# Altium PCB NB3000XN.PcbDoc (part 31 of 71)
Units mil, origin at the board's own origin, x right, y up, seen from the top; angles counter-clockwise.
Board outline 9527.56 x 6929.77 mil, 6 copper layers (Top Layer, GND+SHIELD, MidLayer1, MidLayer2, P2 - 3V3+5V0, Bottom Layer), stack 62.375 mil thick; 832 components, 1027 nets, 4655 pads, 4981 vias.
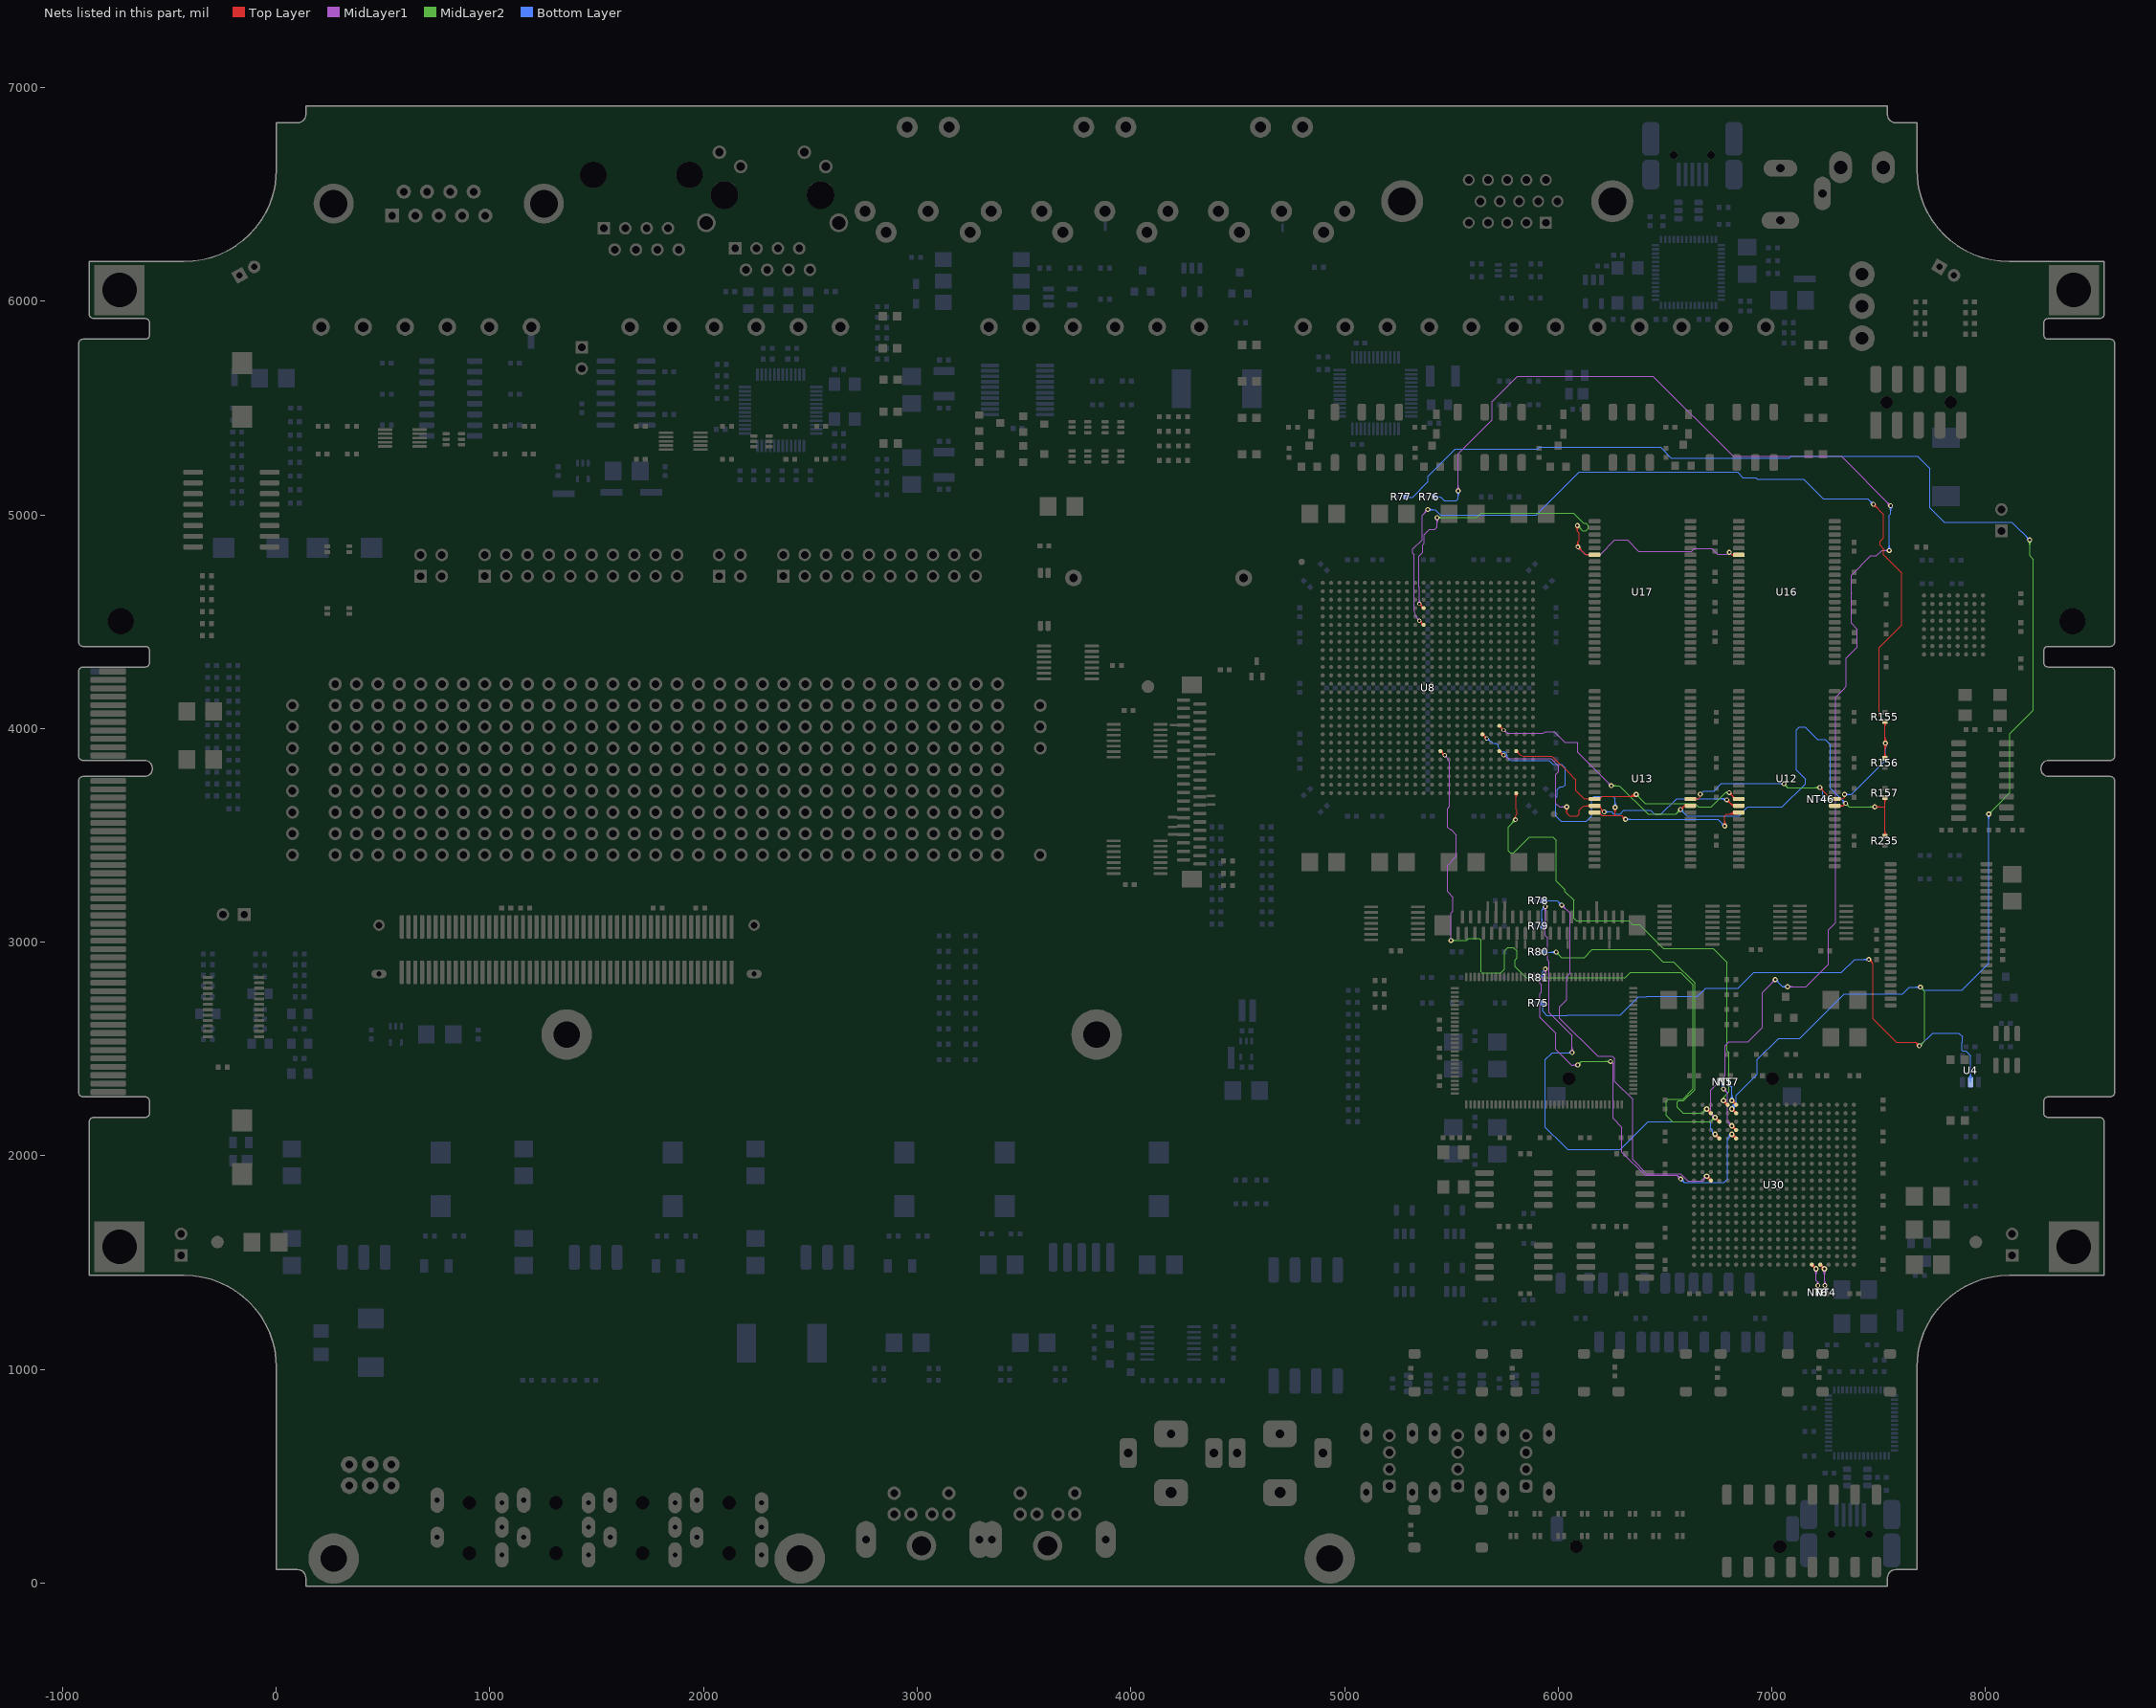
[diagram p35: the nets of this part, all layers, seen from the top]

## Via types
v1: diameter 23, hole 11.81, Top Layer to Bottom Layer, 3672 vias
v2: diameter 26, hole 11.81, Top Layer to Bottom Layer, 461 vias
v3: diameter 19, hole 11.81, Top Layer to Bottom Layer, tented both sides, 396 vias
v4: diameter 23.62, hole 11.81, Top Layer to Bottom Layer, 288 vias
v5: diameter 20, hole 11.81, Top Layer to Bottom Layer, 91 vias
v6: diameter 23, hole 11.81, Top Layer to Bottom Layer, tented both sides, 50 vias
v7: diameter 31, hole 11.81, Top Layer to Bottom Layer, 15 vias
v8: diameter 27.56, hole 11.81, Top Layer to Bottom Layer, tented both sides, 4 vias
v9: diameter 29, hole 11.81, Top Layer to Bottom Layer, 3 vias
v10: diameter 21, hole 11.81, Top Layer to Bottom Layer, 1 vias

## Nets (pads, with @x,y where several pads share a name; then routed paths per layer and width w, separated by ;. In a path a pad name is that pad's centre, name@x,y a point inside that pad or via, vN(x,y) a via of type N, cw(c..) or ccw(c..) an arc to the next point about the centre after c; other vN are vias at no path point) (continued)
DB_MEM.BUS_SDRAM_CKE: R157.2 R235.1 U8.V22 U12.37 U13.37 | length 3869.1
  Top Layer w4: U8.V22@5724.65,4005.33 cw(c5724.65,3987.23) 5737.45,4000.03 cw(c5750.25,4012.83) U8.V22@5732.15,4012.83 ; U8.V22@5724.65,4005.49 cw(c5724.65,3987.77) 5737.18,4000.3 cw(c5749.71,4012.83) U8.V22@5731.99,4012.83 ; U8.V22@5724.65,4012.83 v3(5744.33,3993.15) ; v1(6572.86,3621.04) 6590.83,3639.02 ; v1@6572.86,3626.54 ccw(c6572.86,3639.82) 6582.25,3630.43 ccw(c6591.64,3621.04) v1@6578.36,3621.04 ; v1@6572.86,3630.54 ccw(c6572.86,3653.48) 6589.07,3637.26 ccw(c6605.29,3621.04) v1@6582.36,3621.04 ; v1@6576.21,3624.4 cw(c6601.85,3598.76) U13.37@6601.85,3635.02 ; 6583.04,3631.22 cw(c6601.85,3612.41) U13.37@6601.85,3639.02 ; 6589.87,3638.05 cw(c6601.85,3626.07) U13.37@6601.85,3643.02 ; U13.37@6594.24,3636.54 ccw(c6590.83,3635.43) 6590.83,3639.02 ; U13.37@6594.24,3641.49 cw(c6590.83,3642.6) 6590.83,3639.02 ; U13.37@6619.41,3639.02 6590.83,3639.02 ; U12.37@7294.41,3639.02 7334.17,3639.02 v1(7345.19,3650.04) ; U12.37@7317.63,3633.36 cw(c7331.28,3619.7) 7331.28,3639.02 cw(c7331.28,3658.33) U12.37@7317.63,3644.67 ; v1(7481.86,3633.37) 7528.37,3633.37 7530,3635 ; v1@7485.75,3629.49 cw(c7495.14,3620.1) 7495.14,3633.37 cw(c7495.14,3646.65) v1@7485.75,3637.26 ; v1@7488.57,3626.66 cw(c7504.79,3610.44) 7504.79,3633.37 cw(c7504.79,3656.31) v1@7488.57,3640.09 ; R235.1@7523.41,3502.62 ccw(c7507.5,3518.52) 7530,3518.52 ccw(c7552.5,3518.52) R235.1@7536.59,3502.62 ; R157.2@7523.41,3671.01 cw(c7507.5,3655.1) 7530,3655.1 cw(c7552.5,3655.1) R157.2@7536.59,3671.01 ; R157.2@7524.23,3670.28 cw(c7514.83,3658.38) 7530,3658.38 ; R235.1@7526.24,3499.79 ccw(c7517.16,3508.87) 7530,3508.87 ccw(c7542.84,3508.87) R235.1@7533.76,3499.79 ; R157.2@7526.24,3673.84 cw(c7517.16,3664.76) 7530,3664.76 cw(c7542.84,3664.76) R157.2@7533.76,3673.84 ; R235.1@7530,3496.03 7530,3635 ; R157.2@7535.77,3670.28 ccw(c7545.17,3658.38) 7530,3658.38 ; 5731.53,4005.95 cw(c5718.72,3993.15) 5736.83,3993.15 ccw(c5718.72,3993.15) 5731.53,4005.95 ; 5731.53,4005.95 ccw(c5744.33,4018.76) 5744.33,4000.65 cw(c5744.33,4018.76) 5731.53,4005.95 ; 7530,3635 R157.2@7530,3677.6 7530,3658.37
  MidLayer1 w4: v3@5744.98,3985.68 cw(c5746.56,3967.64) 5758.2,3981.51 cw(c5769.84,3995.38) v3@5751.8,3993.8 ; 5757.91,3981.76 ccw(c5767.84,3991.69) 5767.84,3977.64 5861.38,3977.64 5910,3977.64 5920,3977.64 5931.48,3977.64 5938.99,3985.15 5982.91,3985.15 6031.69,3936.37 6088.52,3936.37 6091.19,3933.71 6091.19,3889.71 6114.19,3866.71 v1(6248.52,3732.37) ; v1@6239.02,3732.37 ccw(c6216.09,3732.37) 6232.31,3748.59 ccw(c6248.52,3764.81) v1@6248.52,3741.87 ; v1@6243.02,3732.37 ccw(c6229.75,3732.37) 6239.14,3741.76 ccw(c6248.52,3751.15) v1@6248.52,3737.87
  MidLayer2 w4: v1(6248.52,3732.37) 6287.63,3732.37 6419.96,3600.04 6551.86,3600.04 v1(6572.86,3621.04) ; v1@6252.41,3728.49 cw(c6261.8,3719.1) 6261.8,3732.37 cw(c6261.8,3745.65) v1@6252.41,3736.26 ; v1@6255.24,3725.66 cw(c6271.46,3709.44) 6271.46,3732.37 cw(c6271.46,3755.31) v1@6255.24,3739.09 ; v1@6563.36,3621.04 cw(c6540.42,3621.04) 6556.64,3604.82 cw(c6572.86,3588.61) v1@6572.86,3611.54 ; v1@6567.36,3621.04 cw(c6554.08,3621.04) 6563.47,3611.65 cw(c6572.86,3602.26) v1@6572.86,3615.54 ; v1@7345.19,3640.54 cw(c7345.19,3617.61) 7361.41,3633.82 cw(c7377.63,3650.04) v1@7354.69,3650.04 ; v1@7345.19,3644.54 cw(c7345.19,3631.26) 7354.58,3640.65 cw(c7363.97,3650.04) v1@7350.69,3650.04 ; v1(7345.19,3650.04) 7361.86,3633.37 v1(7481.86,3633.37) ; v1@7475.14,3626.66 ccw(c7458.92,3610.44) 7458.92,3633.37 ccw(c7458.92,3656.31) v1@7475.14,3640.09 ; v1@7477.97,3629.49 ccw(c7468.58,3620.1) 7468.58,3633.37 ccw(c7468.58,3646.65) v1@7477.97,3637.26
  Bottom Layer w4: v1@6572.86,3611.54 cw(c6572.86,3588.61) 6589.07,3604.82 cw(c6605.29,3621.04) v1@6582.36,3621.04 ; v1@6572.86,3615.54 cw(c6572.86,3602.26) 6582.25,3611.65 cw(c6591.64,3621.04) v1@6578.36,3621.04 ; v1(6572.86,3621.04) 6602.19,3591.71 6845.54,3591.71 6887.21,3633.37 7048.52,3633.37 7156.86,3741.71 7156.86,3763.37 7115.19,3805.04 7115.19,3994.37 7129.19,4008.37 7155.86,4008.37 7214.19,3950.04 7248.52,3950.04 7273.52,3925.04 7273.52,3721.71 v1(7345.19,3650.04) ; v1@7335.69,3650.04 ccw(c7312.76,3650.04) 7328.97,3666.26 ccw(c7345.19,3682.48) v1@7345.19,3659.54 ; v1@7339.69,3650.04 ccw(c7326.41,3650.04) 7335.8,3659.43 ccw(c7345.19,3668.82) v1@7345.19,3655.54
DB_MEM.BUS_SDRAM_CLK: NT46.2 R155.2 R156.1 U8.F13 U12.38 U13.38 | length 6403.5
  Top Layer w4: v3(5350.63,4504.96) U8.F13@5370.31,4485.28 ; U8.F13@5362.81,4485.28 ccw(c5344.71,4485.28) 5357.51,4498.08 ccw(c5370.31,4510.88) U8.F13@5370.31,4492.78 ; U8.F13@5362.97,4485.28 ccw(c5345.25,4485.28) 5357.78,4497.81 ccw(c5370.31,4510.34) U8.F13@5370.31,4492.62 ; U13.38@6619.41,3670.51 6655.99,3670.51 ; U13.38@6642.69,3664.92 cw(c6655.99,3651.89) 6655.99,3670.51 ; U13.38@6642.69,3676.11 ccw(c6655.99,3689.13) 6655.99,3670.51 ; v1(6665.19,3693.04) 6665.19,3679.71 6655.99,3670.51 ; v1@7224.86,3714.54 cw(c7224.86,3691.61) 7241.07,3707.82 cw(c7257.29,3724.04) v1@7234.36,3724.04 ; v1@7224.86,3718.54 cw(c7224.86,3705.26) 7234.25,3714.65 cw(c7243.64,3724.04) v1@7230.36,3724.04 ; v1(7224.86,3724.04) 7265.19,3683.71 7265.19,3670.51 ; U12.38@7269.39,3667.63 ccw(c7265.19,3666.01) 7265.19,3670.51 ; U12.38@7269.39,3673.39 cw(c7265.19,3675.01) 7265.19,3670.51 ; U12.38@7317.63,3664.85 cw(c7331.28,3651.2) 7331.28,3670.51 cw(c7331.28,3689.83) U12.38@7317.63,3676.17 ; v1(7340.19,3691.71) 7340.19,3678.51 7332.19,3670.51 U12.38@7294.41,3670.51 7265.19,3670.51 ; v1@7474.86,5040.54 cw(c7474.86,5017.61) 7491.07,5033.82 cw(c7507.29,5050.04) v1@7484.36,5050.04 ; v1@7474.86,5044.54 cw(c7474.86,5031.26) 7484.25,5040.65 cw(c7493.64,5050.04) v1@7480.36,5050.04 ; v1(7474.86,5050.04) 7523.52,5001.37 7523.52,4892.81 7507.19,4876.48 7507.19,4857.62 7523.52,4841.29 7523.52,4812.73 7606.86,4729.39 7606.86,4483.37 7502.19,4378.71 7502.19,4061.63 R155.2@7530,4033.82 v1@7530,3933.71 ; 7513.25,4050.57 cw(c7496.5,4033.82) R155.2@7520.19,4033.82 ; 7514.44,4049.38 ccw(c7529.51,4064.45) R155.2@7529.51,4043.14 ; R155.2@7520.08,4043.74 cw(c7510.16,4033.82) R155.2@7524.19,4033.82 ; R155.2@7521.27,4042.55 ccw(c7529.51,4050.79) R155.2@7529.51,4039.14 ; R156.1@7523.41,3867.26 ccw(c7507.5,3883.17) 7530,3883.17 ccw(c7552.5,3883.17) R156.1@7536.59,3867.26 ; R155.2@7523.41,4027.23 cw(c7507.5,4011.32) 7530,4011.32 cw(c7552.5,4011.32) R155.2@7536.59,4027.23 ; v1@7525.14,3925.32 cw(c7513.41,3913.59) 7530,3913.59 ; v1@7525.14,3938.76 ccw(c7513.41,3950.49) 7530,3950.49 ; R156.1@7526.24,3864.43 ccw(c7517.16,3873.51) 7530,3873.51 ccw(c7542.84,3873.51) R156.1@7533.76,3864.43 ; R155.2@7526.24,4030.06 cw(c7517.16,4020.98) 7530,4020.98 cw(c7542.84,4020.98) R155.2@7533.76,4030.06 ; R156.1@7530,3860.67 v1@7530,3932.04 ; 7530,3904.62 cw(c7559.28,3904.62) v1@7538.57,3925.32 ; 7530,3914.28 cw(c7549.62,3914.28) v1@7535.75,3928.15 ; 7530,3949.8 ccw(c7549.62,3949.8) v1@7535.75,3935.93 ; 7530,3959.46 ccw(c7559.28,3959.46) v1@7538.57,3938.76 ; 5363.43,4492.16 cw(c5376.24,4504.96) 5358.13,4504.96 ccw(c5376.24,4504.96) 5363.43,4492.16 ; 5363.43,4492.16 ccw(c5350.63,4479.35) 5350.63,4497.46 cw(c5350.63,4479.35) 5363.43,4492.16
  MidLayer1 w4: 5326.77,4581.77 5326.77,4567.84 ; v3@5343.16,4505.61 ccw(c5325.12,4507.19) 5338.99,4518.83 ; v3@5351.28,4512.43 cw(c5352.86,4530.47) 5338.99,4518.83 ; v1@5380.36,5025.04 cw(c5357.42,5025.04) 5373.64,5008.82 cw(c5389.86,4992.61) v1@5389.86,5015.54 ; v1@5384.36,5025.04 cw(c5371.08,5025.04) 5380.47,5015.65 cw(c5389.86,5006.26) v1@5389.86,5019.54 ; v1(5389.86,5025.04) 5362.86,4998.04 5362.86,4884.04 5321.19,4842.37 5319.17,4840.35 5319.17,4821 5326.77,4813.4 5326.77,4724.74 5326.77,4720 5326.77,4710 5326.77,4661.38 5326.77,4641.96 5326.77,4567.84 ; 5326.77,4567.84 5326.77,4548.34 ccw(c5368.5,4548.34) 5338.99,4518.83
  MidLayer2 w4: v1@7056.86,3732.21 cw(c7056.86,3711.69) 7071.37,3726.2 ; v1@7056.86,3736.21 cw(c7056.86,3725.34) 7064.54,3733.03 ; v1@7056.86,3740.71 7073.52,3724.04 v1(7224.86,3724.04) ; v1@7062.35,3741.53 ccw(c7076.5,3741.08) 7066.49,3731.07 ; v1@7066.35,3741.4 ccw(c7089.16,3740.67) 7073.02,3724.54 ; v1@7218.14,3717.32 ccw(c7201.92,3701.11) 7201.92,3724.04 ccw(c7201.92,3746.98) v1@7218.14,3730.76 ; v1@7220.97,3720.15 ccw(c7211.58,3710.76) 7211.58,3724.04 ccw(c7211.58,3737.32) v1@7220.97,3727.93
  Bottom Layer w4: v1(5389.86,5025.04) 5424.04,5025.04 5449.37,4999.71 5897.58,4999.71 6097.92,5200.04 6839.84,5200.04 6865.17,5174.71 6924.47,5174.71 6932.47,5166.71 7148.52,5166.71 7240.19,5075.04 7449.86,5075.04 v1(7474.86,5050.04) ; v1@5393.75,5021.15 cw(c5403.14,5011.76) 5403.14,5025.04 cw(c5403.14,5038.32) v1@5393.75,5028.93 ; v1@5396.57,5018.32 cw(c5412.79,5002.11) 5412.79,5025.04 cw(c5412.79,5047.98) v1@5396.57,5031.76 ; v1(6665.19,3693.04) 6680.19,3708.04 6729.15,3708.04 6763.82,3742.71 7055.86,3742.71 v1(7056.86,3741.71) ; 7031.51,3742.71 cw(c7031.51,3716.36) v1@7050.14,3734.99 ; 7036.34,3742.71 ccw(c7036.34,3762.23) v1@7050.14,3748.43 ; 7041.16,3742.71 cw(c7041.16,3726.02) v1@7052.97,3737.82 ; v1(7224.86,3724.04) 7239,3709.9 NT46.2@7239,3669 ; NT46.2@7236.17,3671.83 ccw(c7229.34,3678.66) 7239,3678.66 ccw(c7248.66,3678.66) NT46.2@7241.83,3671.83 ; v1(7340.19,3691.71) 7373.52,3691.71 7531.86,3850.04 v1(7531.86,3932.04) ; v1@7344.08,3687.82 cw(c7353.47,3678.43) 7353.47,3691.71 cw(c7353.47,3704.99) v1@7344.08,3695.6 ; v1@7346.91,3684.99 cw(c7363.13,3668.77) 7363.13,3691.71 cw(c7363.13,3714.64) v1@7346.91,3698.43 ; v1@7465.36,5050.04 ccw(c7442.42,5050.04) 7458.64,5066.26 ccw(c7474.86,5082.48) v1@7474.86,5059.54 ; v1@7469.36,5050.04 ccw(c7456.08,5050.04) 7465.47,5059.43 ccw(c7474.86,5068.82) v1@7474.86,5055.54 ; v1@7525.14,3925.32 cw(c7508.92,3909.11) 7531.86,3909.11 cw(c7554.79,3909.11) v1@7538.57,3925.32 ; v1@7527.97,3928.15 cw(c7518.58,3918.76) 7531.86,3918.76 cw(c7545.14,3918.76) v1@7535.75,3928.15
DB_MEM.BUS_SDRAM_NCAS: U8.AA24 U12.17 U13.17 | length 1676.9
  Top Layer w4: U13.17@6147.37,3664.85 ccw(c6133.72,3651.2) 6133.72,3670.51 ccw(c6133.72,3689.83) U13.17@6147.37,3676.17 ; U13.17@6188.81,3674.46 ccw(c6190.83,3686.56) 6199.51,3677.88 ; U13.17@6189.47,3678.4 ccw(c6192.41,3695.97) 6205,3683.37 ; U13.17@6196.15,3670.51 cw(c6205.84,3670.51) 6198.99,3677.36 ; 6322.14,3683.37 ccw(c6322.14,3734.76) v1@6358.47,3698.43 ; 6331.79,3683.37 ccw(c6331.79,3725.1) v1@6361.3,3695.6 ; 6341.45,3683.37 ccw(c6341.45,3715.45) v1@6364.13,3692.77 ; 6351.11,3683.37 ccw(c6351.11,3705.79) v1@6366.96,3689.94 ; v1(6365.19,3691.71) 6365.19,3685.04 6363.52,3683.37 6205,3683.37 ; v1@6800.52,3690.54 cw(c6800.52,3667.61) 6816.74,3683.82 cw(c6832.96,3700.04) v1@6810.02,3700.04 ; v1@6800.52,3694.54 cw(c6800.52,3681.26) 6809.91,3690.65 cw(c6819.3,3700.04) v1@6806.02,3700.04 ; v1(6800.52,3700.04) 6830.05,3670.51 U12.17@6845.59,3670.51 ; 6812.95,3687.62 cw(c6795.84,3670.51) U12.17@6820.03,3670.51 ; 6817.83,3682.74 ccw(c6828.03,3692.94) U12.17@6828.03,3678.51 ; 6819.77,3680.79 cw(c6809.49,3670.51) U12.17@6824.03,3670.51 ; 5815.92,3882.19 ccw(c5843.27,3909.54) 5843.27,3870.86 ; 5815.92,3882.19 ccw(c5843.27,3909.54) 5843.27,3870.86 ; 5815.92,3882.19 ccw(c5803.39,3869.66) 5803.39,3887.38 cw(c5803.39,3869.66) 5815.92,3882.19 ; 5815.92,3882.19 cw(c5828.45,3894.72) 5810.73,3894.72 ccw(c5828.45,3894.72) 5815.92,3882.19 ; 5843.27,3870.86 5910,3870.86 5920,3870.86 5971.06,3870.86 6052.7,3789.22 6074.88,3767.04 ; 6074.88,3767.04 6081.86,3760.06 ; 6074.88,3767.04 6081.86,3760.06 ; 6081.86,3760.06 6081.86,3710.04 6108.52,3683.37 6121.39,3670.51 U13.17@6170.59,3670.51 6192.14,3670.51 6205,3683.37
  MidLayer2 w4: v1@6365.19,3682.21 cw(c6365.19,3659.27) 6381.41,3675.49 cw(c6397.63,3691.71) v1@6374.69,3691.71 ; v1@6365.19,3686.21 cw(c6365.19,3672.93) 6374.58,3682.32 cw(c6383.97,3691.71) v1@6370.69,3691.71 ; v1(6365.19,3691.71) 6406.86,3650.04 6640.19,3650.04 6656.86,3633.37 6716.86,3633.37 6783.52,3700.04 ; v1@6792.43,3695.06 ccw(c6783.52,3689.58) 6783.52,3700.04 ; v1@6792.43,3705.02 cw(c6783.52,3710.5) 6783.52,3700.04 ; v1(6800.52,3700.04) 6783.52,3700.04
DB_MEM.BUS_SDRAM_NCS: U8.W20 U12.19 U13.19 | length 2619.8
  Top Layer w4: U8.W20@5645.91,3965.96 cw(c5645.91,3947.86) 5658.71,3960.66 cw(c5671.51,3973.46) U8.W20@5653.41,3973.46 ; U8.W20@5645.91,3966.12 cw(c5645.91,3948.4) 5658.44,3960.93 cw(c5670.97,3973.46) U8.W20@5653.25,3973.46 ; U8.W20@5645.91,3973.46 v3(5665.59,3953.78) ; U13.19@6170.59,3607.52 6189.86,3607.52 6205,3592.37 6265.19,3592.37 ; U13.19@6188.15,3599.52 cw(c6188.15,3576.09) 6204.72,3592.66 ; U13.19@6188.15,3603.52 cw(c6188.15,3589.75) 6197.89,3599.49 ; U13.19@6196.15,3607.52 ccw(c6211.35,3607.52) 6200.6,3596.77 ; v1@6259.81,3624.66 cw(c6243.59,3608.44) 6266.52,3608.44 cw(c6289.46,3608.44) v1@6273.24,3624.66 ; v1@6262.64,3627.49 cw(c6253.25,3618.1) 6266.52,3618.1 cw(c6279.8,3618.1) v1@6270.41,3627.49 ; v1@6265.19,3631.37 v1(6266.52,3631.37) 6266.52,3593.71 6265.19,3592.37 ; v1@6305.69,3575.04 ccw(c6282.76,3575.04) 6298.97,3591.26 ccw(c6315.19,3607.48) v1@6315.19,3584.54 ; v1@6309.69,3575.04 ccw(c6296.41,3575.04) 6305.8,3584.43 ccw(c6315.19,3593.82) v1@6315.19,3580.54 ; v1(6315.19,3575.04) 6297.86,3592.37 6265.19,3592.37 ; v1@6772.81,3550.76 ccw(c6756.59,3566.98) 6779.52,3566.98 ccw(c6802.46,3566.98) v1@6786.24,3550.76 ; v1@6775.64,3547.93 ccw(c6766.25,3557.32) 6779.52,3557.32 ccw(c6792.8,3557.32) v1@6783.41,3547.93 ; v1(6779.52,3544.04) 6779.52,3591.71 6787.86,3600.04 6838.11,3600.04 U12.19@6845.59,3607.52 ; 6790.66,3600.04 ccw(c6790.66,3644.89) U12.19@6822.37,3613.18 ; 6800.32,3600.04 ccw(c6800.32,3635.23) U12.19@6825.2,3610.35 ; 6809.98,3600.04 ccw(c6809.98,3625.58) U12.19@6828.03,3607.52 ; U12.19@6819.63,3600.04 ccw(c6819.63,3615.92) U12.19@6830.86,3604.69 ; 5652.79,3966.58 cw(c5639.98,3953.78) 5658.09,3953.78 ccw(c5639.98,3953.78) 5652.79,3966.58 ; 5652.79,3966.58 ccw(c5665.59,3979.39) 5665.59,3961.28 cw(c5665.59,3979.39) 5652.79,3966.58
  Bottom Layer w4: v3@5666.89,3946.39 cw(c5670.04,3928.56) 5680.42,3943.39 ; v3@5672.98,3955.08 ccw(c5690.81,3958.23) 5680.42,3943.39 ; 6266.52,3655 v1(6266.52,3631.37) 6266.52,3673.48 6256.29,3683.71 6168.5,3683.71 6156.86,3672.06 6156.86,3591.71 6131.86,3566.71 6014.19,3566.71 5989.19,3591.71 5989.19,3675 5996,3681.81 5996,3714 6009.19,3727.19 6022.38,3727.19 6032.81,3737.62 6032.81,3815.75 6015.19,3833.37 5975,3833.37 5957.11,3851.27 5920,3851.27 5910,3851.27 5841.96,3851.27 5783.7,3851.27 cw(c5783.7,3875.04) 5759.93,3875.04 ccw(c5744.33,3875.04) 5744.33,3890.64 cw(c5744.33,3914.41) 5720.56,3914.41 ccw(c5704.96,3914.41) 5704.96,3930.01 cw(c5704.96,3953.78) 5688.15,3936.97 5680.42,3943.39 ; v1(6315.19,3575.04) 6748.52,3575.04 v1(6779.52,3544.04) ; v1@6319.08,3571.15 cw(c6328.47,3561.76) 6328.47,3575.04 cw(c6328.47,3588.32) v1@6319.08,3578.93 ; v1@6321.91,3568.32 cw(c6338.13,3552.11) 6338.13,3575.04 cw(c6338.13,3597.98) v1@6321.91,3581.76 ; v1@6770.02,3544.04 ccw(c6747.09,3544.04) 6763.31,3560.26 ccw(c6779.52,3576.48) v1@6779.52,3553.54 ; v1@6774.02,3544.04 ccw(c6760.75,3544.04) 6770.14,3553.43 ccw(c6779.52,3562.82) v1@6779.52,3549.54 ; 6266.52,3644.65 cw(c6253.25,3644.65) 6262.64,3635.26 ccw(c6253.25,3644.65) 6266.52,3644.65 ; 6266.52,3644.65 ccw(c6279.8,3644.65) 6270.41,3635.26 cw(c6279.8,3644.65) 6266.52,3644.65 ; 6266.52,3654.31 cw(c6243.59,3654.31) 6259.81,3638.09 ccw(c6243.59,3654.31) 6266.52,3654.31 ; 6266.52,3654.31 ccw(c6289.46,3654.31) 6273.24,3638.09 cw(c6289.46,3654.31) 6266.52,3654.31
DB_MEM.BUS_SDRAM_NRAS: U8.AA22 U12.18 U13.18 | length 2151.1
  Top Layer w4: U8.AA22@5724.65,3887.22 cw(c5724.65,3869.12) 5737.45,3881.92 cw(c5750.25,3894.72) U8.AA22@5732.15,3894.72 ; U8.AA22@5724.65,3887.38 cw(c5724.65,3869.66) 5737.18,3882.19 cw(c5749.71,3894.72) U8.AA22@5731.99,3894.72 ; U8.AA22@5724.65,3894.72 v3(5744.33,3875.04) ; v1@6033.47,3626.66 cw(c6017.26,3610.44) 6040.19,3610.44 cw(c6063.13,3610.44) v1@6046.91,3626.66 ; v1@6036.3,3629.49 cw(c6026.91,3620.1) 6040.19,3620.1 cw(c6053.47,3620.1) v1@6044.08,3629.49 ; v1(6040.19,3633.37) 6040.19,3604.81 6053.29,3591.71 6090.19,3591.71 6098.52,3600.04 6098.52,3616.71 6112.76,3630.95 6120.83,3639.02 U13.18@6170.59,3639.02 6186.22,3639.02 6193.6,3631.63 v1(6215.19,3610.04) ; U13.18@6147.37,3633.36 ccw(c6133.72,3619.7) 6133.72,3639.02 ccw(c6133.72,3658.33) U13.18@6147.37,3644.67 ; U13.18@6188.15,3631.02 cw(c6188.15,3616.37) 6198.51,3626.73 ; U13.18@6192.15,3639.02 ccw(c6206.47,3639.02) 6196.34,3628.89 ; U13.18@6196.15,3639.02 ccw(c6220.13,3639.01) 6203.17,3622.06 ; v1@6205.69,3610.04 ccw(c6182.76,3610.04) 6198.97,3626.26 ccw(c6215.19,3642.48) v1@6215.19,3619.54 ; v1@6209.69,3610.04 ccw(c6196.41,3610.04) 6205.8,3619.43 ccw(c6215.19,3628.82) v1@6215.19,3615.54 ; v1@6789.19,3657.21 cw(c6789.19,3634.27) 6805.41,3650.49 cw(c6821.63,3666.71) v1@6798.69,3666.71 ; v1@6789.19,3661.21 cw(c6789.19,3647.93) 6798.58,3657.32 cw(c6807.97,3666.71) v1@6794.69,3666.71 ; v1(6789.19,3666.71) 6816.88,3639.02 ; v1@6795.34,3660.55 ccw(c6828.03,3693.24) U12.18@6828.03,3647.02 ; 6802.17,3653.73 ccw(c6828.03,3679.59) U12.18@6828.03,3643.02 ; 6809,3646.9 ccw(c6828.03,3665.93) U12.18@6828.03,3639.02 ; 6815.83,3640.07 ccw(c6828.03,3652.27) U12.18@6828.03,3635.02 ; U12.18@6820.45,3636.45 ccw(c6816.88,3635.25) 6816.88,3639.02 ; U12.18@6820.45,3641.58 cw(c6816.88,3642.78) 6816.88,3639.02 ; U12.18@6845.59,3639.02 6816.88,3639.02 ; 5731.53,3887.84 cw(c5718.72,3875.04) 5736.83,3875.04 ccw(c5718.72,3875.04) 5731.53,3887.84 ; 5731.53,3887.84 ccw(c5744.33,3900.65) 5744.33,3882.54 cw(c5744.33,3900.65) 5731.53,3887.84
  MidLayer1 w4: v3@5745.63,3867.65 cw(c5748.78,3849.82) 5759.16,3864.65 cw(c5769.55,3879.49) v3@5751.72,3876.34 ; 5759.19,3864.62 ccw(c5776.84,3892.66) 5777.01,3859.53 5861.38,3859.53 5910,3859.53 5920,3859.53 5966.53,3859.53 6003,3823.06 6003,3798.81 5989.19,3785 5989.19,3650.04 6005.86,3633.37 v1(6040.19,3633.37) ; v1@6033.47,3626.66 ccw(c6017.26,3610.44) 6017.26,3633.37 ccw(c6017.26,3656.31) v1@6033.47,3640.09 ; v1@6036.3,3629.49 ccw(c6026.91,3620.1) 6026.91,3633.37 ccw(c6026.91,3646.65) v1@6036.3,3637.26
  Bottom Layer w4: v1(6215.19,3610.04) 6250.21,3610.04 6260.21,3600.04 6290.19,3600.04 6307.19,3617.04 6432.96,3617.04 6449.96,3600.04 ; v1@6219.08,3606.15 cw(c6228.47,3596.76) 6228.47,3610.04 cw(c6228.47,3623.32) v1@6219.08,3613.93 ; v1@6221.91,3603.32 cw(c6238.13,3587.11) 6238.13,3610.04 cw(c6238.13,3632.98) v1@6221.91,3616.76 ; 6450,3600 6449.96,3600.04 ; 6752.57,3672.37 cw(c6752.57,3630.09) v1@6782.47,3659.99 ; 6762.23,3672.37 cw(c6762.23,3639.75) v1@6785.3,3662.82 ; 6771.89,3672.37 cw(c6771.89,3649.41) v1@6788.13,3665.65 ; v1(6789.19,3666.71) 6783.52,3672.37 6554.19,3672.37 6481.86,3600.04 6449.96,3600.04
DB_MEM.BUS_SRAM_NCS: U8.D13 U16.6 U17.6 | length 2993.7
  Top Layer w4: v3(5350.63,4583.7) U8.D13@5370.31,4564.02 ; U8.D13@5362.81,4564.02 ccw(c5344.71,4564.02) 5357.51,4576.82 ccw(c5370.31,4589.62) U8.D13@5370.31,4571.52 ; U8.D13@5362.97,4564.02 ccw(c5345.25,4564.02) 5357.78,4576.55 ccw(c5370.31,4589.08) U8.D13@5370.31,4571.36 ; v1@6083.47,4943.32 cw(c6067.26,4927.11) 6090.19,4927.11 cw(c6113.13,4927.11) v1@6096.91,4943.32 ; v1@6085.47,4856.76 ccw(c6069.26,4872.98) 6092.19,4872.98 ccw(c6115.13,4872.98) v1@6098.91,4856.76 ; v1@6086.3,4946.15 cw(c6076.91,4936.76) 6090.19,4936.76 cw(c6103.47,4936.76) v1@6094.08,4946.15 ; v1@6088.3,4853.93 ccw(c6078.91,4863.32) 6092.19,4863.32 ccw(c6105.47,4863.32) v1@6096.08,4853.93 ; v1(6090.19,4950.04) 6090.19,4923.33 6098.52,4915 6098.52,4880 6092.19,4873.67 v1(6092.19,4850.04) 6129,4813.23 U17.6@6170.59,4813.23 ; v1@6092.19,4840.54 cw(c6092.19,4817.61) 6108.41,4833.82 cw(c6124.63,4850.04) v1@6101.69,4850.04 ; v1@6092.19,4844.54 cw(c6092.19,4831.26) 6101.58,4840.65 cw(c6110.97,4850.04) v1@6097.69,4850.04 ; U17.6@6147.37,4807.57 ccw(c6133.72,4793.91) 6133.72,4813.23 ccw(c6133.72,4832.54) U17.6@6147.37,4818.88 ; v1(6800.86,4825.04) 6812.67,4813.23 ; U16.6@6821.48,4808.64 ccw(c6812.67,4802.48) 6812.67,4813.23 ; U16.6@6821.48,4817.81 cw(c6812.67,4823.97) 6812.67,4813.23 ; U16.6@6845.59,4813.23 6812.67,4813.23 ; 5363.43,4570.9 cw(c5376.24,4583.7) 5358.13,4583.7 ccw(c5376.24,4583.7) 5363.43,4570.9 ; 5363.43,4570.9 ccw(c5350.63,4558.09) 5350.63,4576.2 cw(c5350.63,4558.09) 5363.43,4570.9
  MidLayer1 w4: v3@5345.44,4588.89 ccw(c5332.9,4601.43) 5350.63,4601.43 ccw(c5368.36,4601.43) v3@5355.82,4588.89 ; v3(5350.63,4583.7) 5350.63,4661.38 5347.5,4664.51 5347.5,4710 5347.5,4720 5347.5,4807.35 5365.19,4825.04 5365.19,4858.37 5373.52,4866.71 5373.52,4908.37 5397.69,4932.54 5422.11,4932.54 5432.69,4943.12 5432.69,4950.87 5433.19,4951.37 5433.52,4951.71 v1(5433.52,4987.37) ; v1@5426.81,4980.66 cw(c5410.59,4964.44) 5433.52,4964.44 cw(c5456.46,4964.44) v1@5440.24,4980.66 ; v1@5429.64,4983.49 cw(c5420.25,4974.1) 5433.52,4974.1 cw(c5446.8,4974.1) v1@5437.41,4983.49 ; v1@6092.19,4840.54 cw(c6092.19,4817.61) 6108.41,4833.82 cw(c6124.63,4850.04) v1@6101.69,4850.04 ; v1@6092.19,4844.54 cw(c6092.19,4831.26) 6101.58,4840.65 cw(c6110.97,4850.04) v1@6097.69,4850.04 ; v1(6092.19,4850.04) 6125.52,4816.71 6198.52,4816.71 6265.19,4883.37 6323.52,4883.37 6376.52,4830.37 6510,4830.37 6623.67,4830.37 6635,4841.71 6719.19,4841.71 6745.52,4815.37 6791.19,4815.37 v1(6800.86,4825.04) ; 5350.63,4601.81 cw(c5332.52,4601.81) 5345.33,4589 ccw(c5332.52,4601.81) 5350.63,4601.81 ; 5350.63,4601.81 ccw(c5368.74,4601.81) 5355.93,4589 cw(c5368.74,4601.81) 5350.63,4601.81
  MidLayer2 w4: v1(5433.52,4987.37) 5618.58,4987.37 5639.41,5008.2 6071.84,5008.2 6119.5,4960.54 6130.77,4960.54 6141.02,4950.29 6141.02,4935.79 6130.77,4925.54 6114.69,4925.54 v1@6088,4952.23 ; v1@5437.41,4983.49 cw(c5446.8,4974.1) 5446.8,4987.37 cw(c5446.8,5000.65) v1@5437.41,4991.26 ; v1@5440.24,4980.66 cw(c5456.46,4964.44) 5456.46,4987.37 cw(c5456.46,5010.31) v1@5440.24,4994.09 ; v1@6090.19,4940.54 cw(c6090.19,4917.61) 6106.41,4933.82 cw(c6122.62,4950.04) v1@6099.69,4950.04 ; v1@6090.19,4944.54 cw(c6090.19,4931.26) 6099.58,4940.65 cw(c6108.97,4950.04) v1@6095.69,4950.04
DB_PROGRAM.CCLK: R78.1 U30.V10 | length 2223.1
  Top Layer w8: v2@6695.04,1895.37 cw(c6695.04,1873.64) 6710.4,1889.01 cw(c6725.77,1904.37) v2@6704.04,1904.37 ; v2(6695.04,1904.37) U30.V10@6714.72,1884.68 ; U30.V10@6708.88,1884.68 ccw(c6694.78,1884.68) 6704.75,1894.66 ccw(c6714.72,1904.63) U30.V10@6714.72,1890.53
  MidLayer1 w4: v1@6016.52,3164.21 cw(c6016.52,3141.27) 6032.74,3157.49 cw(c6048.96,3173.71) v1@6026.02,3173.71 ; v1@6016.52,3168.21 cw(c6016.52,3154.93) 6025.91,3164.32 cw(c6035.3,3173.71) v1@6022.02,3173.71 ; v1(6016.52,3173.71) 6054.86,3135.37 6054.86,2853.35 6040.19,2838.69 6040.19,2730.39 6006.86,2697.06 6006.86,2644.69 6184.84,2466.71 6253.19,2466.71 6265.19,2454.71 6265.19,2348.04 6348.52,2264.71 6348.52,1983.37 6415.19,1916.71 6573.52,1916.71 6606.86,1883.37 6674.05,1883.37 v2(6695.04,1904.37) ; v2@6684.04,1904.37 cw(c6657.48,1904.37) 6676.26,1885.59 cw(c6695.04,1866.82) v2@6695.04,1893.37 ; v2@6688.04,1904.37 cw(c6671.14,1904.37) 6683.09,1892.42 cw(c6695.04,1880.47) v2@6695.04,1897.37
  Bottom Layer w4: R78.1@5928.18,3195 5995.23,3195 v1(6016.52,3173.71) ; R78.1@5931.94,3191.24 cw(c5941.02,3182.16) 5941.02,3195 cw(c5941.02,3207.84) R78.1@5931.94,3198.76 ; R78.1@5934.77,3188.41 cw(c5950.68,3172.5) 5950.68,3195 cw(c5950.68,3217.5) R78.1@5934.77,3201.59 ; v1@6007.02,3173.71 ccw(c5984.09,3173.71) 6000.31,3189.93 ccw(c6016.52,3206.14) v1@6016.52,3183.21 ; v1@6011.02,3173.71 ccw(c5997.75,3173.71) 6007.14,3183.1 ccw(c6016.52,3192.49) v1@6016.52,3179.21
DB_PROGRAM.DIN: U8.AF24 U30.T1 | length 2629.5
  Top Layer w4: U8.AF24@5798.08,3692.57 cw(c5785.28,3679.77) 5803.39,3679.77 cw(c5821.49,3679.77) U8.AF24@5808.69,3692.57 ; U8.AF24@5798.19,3692.68 cw(c5785.66,3680.15) 5803.39,3680.15 cw(c5821.11,3680.15) U8.AF24@5808.58,3692.68 ; v1(5799.86,3573.37) 5799.86,3591.17 5807.69,3599 5807.69,3618.96 5803.39,3623.26 5803.39,3660 5803.39,3670 U8.AF24@5803.39,3697.87
  Top Layer w8: v2@6773.78,2249.7 cw(c6773.78,2227.97) 6789.14,2243.34 cw(c6804.51,2258.7) v2@6782.78,2258.7 ; v2(6773.78,2258.7) U30.T1@6793.46,2239.02 ; U30.T1@6787.62,2239.02 ccw(c6773.52,2239.02) 6783.49,2248.99 ccw(c6793.46,2258.96) U30.T1@6793.46,2244.86
  MidLayer2 w4: v1@5790.36,3573.37 cw(c5767.42,3573.37) 5783.64,3557.16 cw(c5799.86,3540.94) v1@5799.86,3563.87 ; v1@5794.36,3573.37 cw(c5781.08,3573.37) 5790.47,3563.99 cw(c5799.86,3554.6) v1@5799.86,3567.87 ; v1(5799.86,3573.37) 5766.86,3540.37 5766.86,3428.14 5776.63,3418.37 5791.86,3418.37 5865.19,3491.71 5975.19,3491.71 5990.86,3476.04 5990.86,3286.04 6031.86,3245.04 6031.86,3238.14 6073.52,3196.48 6073.52,3111.35 6085.17,3099.71 6331.48,3099.71 6347.82,3083.37 6380.09,3083.37 6492.43,2971.04 6726.52,2971.04 6790.86,2906.71 6790.86,2491.04 6798.52,2483.37 6798.52,2300.04 6773.78,2275.3 ; v2@6769.5,2268.83 ccw(c6766.76,2275.3) 6773.78,2275.3 ; v2(6773.78,2258.7) 6773.78,2275.3 ; v2@6778.06,2268.83 cw(c6780.8,2275.3) 6773.78,2275.3
DB_PROGRAM.DONE: R75.1 R77.1 U4.2 U30.R2 | length 10924.7
  Top Layer w4: v1@7453.86,2910.21 cw(c7453.86,2887.27) 7470.07,2903.49 cw(c7486.29,2919.71) v1@7463.36,2919.71 ; v1@7453.86,2914.21 cw(c7453.86,2900.93) 7463.25,2910.32 cw(c7472.64,2919.71) v1@7459.36,2919.71 ; v1(7453.86,2919.71) 7473.52,2900.04 7473.52,2641.71 7550.09,2565.14 7583.67,2531.57 7673.43,2531.57 v1(7690,2515) ; v1@7680.5,2515 ccw(c7657.56,2515) 7673.78,2531.22 ccw(c7690,2547.43) v1@7690,2524.5 ; v1@7684.5,2515 ccw(c7671.22,2515) 7680.61,2524.39 ccw(c7690,2533.78) v1@7690,2520.5
  Top Layer w8: v2@6813.15,2210.33 cw(c6813.15,2188.6) 6828.51,2203.97 cw(c6843.88,2219.33) v2@6822.15,2219.33 ; v2(6813.15,2219.33) U30.R2@6832.83,2199.65 ; U30.R2@6826.99,2199.65 ccw(c6812.89,2199.65) 6822.86,2209.62 ccw(c6832.83,2219.59) U30.R2@6832.83,2205.49
  MidLayer2 w4: v1@7690,2520.5 ccw(c7690,2540.58) 7704.2,2526.38 ; v1@7690,2524.5 ccw(c7690,2554.23) 7711.03,2533.21 ; v1@7692.82,2515 7715.52,2537.71 7715.52,2769.48 v1(7695,2790) ; v1@7695,2780.5 cw(c7695,2757.56) 7711.22,2773.78 cw(c7727.44,2790) v1@7704.5,2790 ; v1@7695,2784.5 cw(c7695,2771.22) 7704.39,2780.61 cw(c7713.78,2790) v1@7700.5,2790 ; v1@7699.5,2515 cw(c7715.64,2515) 7704.23,2526.41 ; v1(8015.19,3600.04) 8060.07,3644.93 ; v1@8015.19,3605.54 ccw(c8015.19,3618.82) 8024.58,3609.43 ccw(c8033.97,3600.04) v1@8020.69,3600.04 ; v1@8015.19,3609.54 ccw(c8015.19,3632.48) 8031.41,3616.26 ccw(c8047.63,3600.04) v1@8024.69,3600.04 ; 8060,3645 8114.86,3699.86 8114.86,3977.06 8223.52,4085.73 8223.52,4791.71 8206.86,4808.37 v1(8206.86,4883.37) ; v1@8200.14,4876.66 cw(c8183.92,4860.44) 8206.86,4860.44 cw(c8229.79,4860.44) v1@8213.57,4876.66 ; v1@8202.97,4879.49 cw(c8193.58,4870.1) 8206.86,4870.1 cw(c8220.14,4870.1) v1@8210.75,4879.49
  Bottom Layer w4: R77.1@5286.18,5085 5286.18,5083.37 5318.52,5083.37 5391.52,5156.37 5391.52,5181.52 5517.5,5307.5 5903.31,5307.5 5913.19,5317.37 6478,5317.37 6528.67,5266.71 7081.67,5266.71 7090,5275.04 7682.33,5275.04 7740.19,5217.18 7740.19,5033.37 7806.86,4966.71 8123.52,4966.71 v1(8206.86,4883.37) ; R77.1@5289.94,5088.27 ccw(c5301.76,5100.08) 5301.76,5083.37 ; R77.1@5292.77,5077.92 cw(c5305.94,5064.75) 5305.94,5083.37 ; R77.1@5292.77,5091.1 ccw(c5311.41,5109.74) 5311.41,5083.37 ; R75.1@5921.59,2707.92 cw(c5905.68,2692.01) 5928.18,2692.01 cw(c5950.68,2692.01) R75.1@5934.77,2707.92 ; R75.1@5924.42,2710.75 cw(c5915.34,2701.67) 5928.18,2701.67 cw(c5941.02,2701.67) R75.1@5931.94,2710.75 ; R75.1@5928.18,2715 5928.18,2676.82 5946.96,2658.04 6041.96,2658.04 ; 6041.96,2658.37 6290.19,2658.37 6375.86,2744.04 6413.86,2744.04 6416.86,2747.04 6652.52,2747.04 6681.86,2776.37 6689.19,2783.71 6841.13,2783.71 6915.8,2858.37 7325.9,2858.37 7387.23,2919.71 v1(7453.86,2919.71) ; v2@6812.17,2219.13 cw(c6829.59,2222.64) 6817.03,2235.21 ; v2@6815.19,2219.33 6815.19,2233.37 6832.86,2251.04 ; v2@6816.09,2219.92 cw(c6838.38,2224.41) 6822.3,2240.49 ; v2@6820.01,2220.71 cw(c6847.16,2226.18) 6827.58,2245.76 ; v2@6823.93,2221.5 cw(c6855.95,2227.95) 6832.86,2251.04 ; v1@7447.14,2912.99 ccw(c7430.92,2896.77) 7430.92,2919.71 ccw(c7430.92,2942.64) v1@7447.14,2926.43 ; v1@7449.97,2915.82 ccw(c7440.58,2906.43) 7440.58,2919.71 ccw(c7440.58,2932.99) v1@7449.97,2923.6 ; v1@7688.28,2783.28 ccw(c7672.06,2767.06) 7672.06,2790 ccw(c7672.06,2812.93) v1@7688.28,2796.72 ; v1@7690,2520.5 ccw(c7690,2540.58) 7704.2,2526.38 ; v1@7690,2524.5 ccw(c7690,2554.23) 7711.03,2533.21 ; v1@7691.11,2786.11 ccw(c7681.72,2776.72) 7681.72,2790 ccw(c7681.72,2803.28) v1@7691.11,2793.89 ; v1@7692.82,2515 7752.86,2575.04 7874.52,2575.04 7891.52,2558.04 7891.52,2533.37 7890.19,2532.04 7890.19,2494.37 7892.86,2491.71 7906.86,2491.71 7930,2468.56 U4.2@7930,2344.88 ; v1@7699.5,2515 cw(c7715.64,2515) 7704.23,2526.41 ; U4.2@7923.06,2365.6 ccw(c7906.31,2382.35) 7930,2382.35 ccw(c7953.68,2382.35) U4.2@7936.94,2365.6 ; U4.2@7925.89,2362.77 ccw(c7915.97,2372.69) 7930,2372.69 ccw(c7944.03,2372.69) U4.2@7934.11,2362.77 ; v1@8008.47,3593.32 cw(c7992.26,3577.11) 8015.19,3577.11 cw(c8038.13,3577.11) v1@8021.91,3593.32 ; v1@8011.3,3596.15 cw(c8001.91,3586.76) 8015.19,3586.76 cw(c8028.47,3586.76) v1@8019.08,3596.15 ; v1(8015.19,3600.04) 8015.19,2900.65 7889.58,2775.04 7709.96,2775.04 v1(7695,2790) 7643.84,2790 7611.88,2758.04 7339.86,2758.04 7131.86,2550.04 7031.86,2550.04 6931.86,2450.04 6931.86,2382.37 6832.86,2283.37 6832.86,2251.04 ; v1@8197.36,4883.37 ccw(c8174.42,4883.37) 8190.64,4899.59 ccw(c8206.86,4915.81) v1@8206.86,4892.87 ; v1@8201.36,4883.37 ccw(c8188.08,4883.37) 8197.47,4892.76 ccw(c8206.86,4902.15) v1@8206.86,4888.87
DB_PROGRAM.ID0: NT4.1 U30.E20 | length 340.4
  Top Layer w8: U30.E20@7226.54,1485.14 cw(c7226.54,1471.04) 7236.51,1481.01 cw(c7246.48,1490.98) U30.E20@7232.38,1490.98 ; U30.E20@7226.54,1490.98 v2(7246.22,1471.3) ; v2@7237.22,1471.3 ccw(c7215.49,1471.3) 7230.86,1486.66 ccw(c7246.22,1502.03) v2@7246.22,1480.3
  MidLayer1 w4: v2@7238.44,1463.52 cw(c7219.66,1444.74) 7246.22,1444.74 cw(c7272.78,1444.74) v2@7254,1463.52 ; v2@7241.27,1466.35 cw(c7229.32,1454.4) 7246.22,1454.4 ; v1@7243.98,1401.38 ccw(c7239.8,1409.04) 7248.52,1409.04 ; 7246.22,1454.4 cw(c7263.12,1454.4) v2@7251.17,1466.35 ; v2(7246.22,1471.3) 7246.22,1411.34 7248.52,1409.04 ; v1(7248.52,1393.04) 7248.52,1409.04 ; v1@7253.07,1401.38 cw(c7257.25,1409.04) 7248.52,1409.04
  Bottom Layer w4: v1@7244.88,1384.27 cw(c7238.59,1369.11) NT4.1@7255,1369.11 ; v1@7246.41,1387.96 cw(c7241.07,1375.1) NT4.1@7255,1375.1 ; v1@7247.95,1391.66 cw(c7243.56,1381.09) 7255,1381.09 ; v1(7248.52,1393.04) 7255,1386.56 NT4.1@7255,1370 ; NT4.1@7252.17,1377.33 ccw(c7245.34,1384.16) 7255,1384.16 ccw(c7264.66,1384.16) NT4.1@7257.83,1377.33
DB_PROGRAM.ID1: NT5.1 U30.R4 | length 467.6
  Top Layer w8: v2@6813.15,2131.59 cw(c6813.15,2109.86) 6828.51,2125.23 cw(c6843.88,2140.59) v2@6822.15,2140.59 ; v2(6813.15,2140.59) U30.R4@6832.83,2120.91 ; U30.R4@6826.99,2120.91 ccw(c6812.89,2120.91) 6822.86,2130.88 ccw(c6832.83,2140.85) U30.R4@6832.83,2126.75
  MidLayer1 w4: v1@6773.52,2303.87 cw(c6773.52,2280.94) 6789.74,2297.16 cw(c6805.96,2313.37) v1@6783.02,2313.37 ; v1@6773.52,2307.87 cw(c6773.52,2294.6) 6782.91,2303.99 cw(c6792.3,2313.37) v1@6779.02,2313.37 ; v1(6773.52,2313.37) 6792.86,2294.04 6792.86,2160.88 v2(6813.15,2140.59) ; v2@6802.15,2140.59 ccw(c6775.59,2140.59) 6794.37,2159.37 ccw(c6813.15,2178.14) v2@6813.15,2151.59 ; v2@6806.15,2140.59 ccw(c6789.25,2140.59) 6801.2,2152.54 ccw(c6813.15,2164.49) v2@6813.15,2147.59
  Bottom Layer w4: v1@6766.81,2320.09 ccw(c6759.1,2327.8) NT5.1@6770,2327.8 ; NT5.1@6767.92,2327.08 cw(c6765.65,2323.38) v1@6770,2323.38 ; NT5.1@6770,2328.36 ccw(c6781.45,2328.36) v1@6776.1,2318.24 ; NT5.1@6770,2335 ccw(c6784.96,2335) v1@6777.97,2321.77 ; NT5.1@6770,2335 v1@6770,2323.37 ; NT5.1@6772.08,2327.09 ccw(c6774.35,2323.38) v1@6770,2323.38 ; v1(6773.52,2313.37) 6773.52,2319.85 v1@6770,2323.37
DB_PROGRAM.ID2: NT6.1 U30.F20 | length 291.1
  Top Layer w8: U30.F20@7187.17,1485.14 cw(c7187.17,1471.04) 7197.14,1481.01 cw(c7207.11,1490.98) U30.F20@7193.01,1490.98 ; U30.F20@7187.17,1490.98 v2(7206.85,1471.3) ; v2@7197.85,1471.3 ccw(c7176.12,1471.3) 7191.49,1486.66 ccw(c7206.85,1502.03) v2@7206.85,1480.3
  MidLayer1 w4: v2@7199.07,1463.52 cw(c7180.29,1444.74) 7206.85,1444.74 cw(c7233.41,1444.74) v2@7214.63,1463.52 ; v2@7201.9,1466.35 cw(c7189.95,1454.4) 7206.85,1454.4 ; 7206.85,1454.4 cw(c7223.75,1454.4) v2@7211.8,1466.35 ; v2(7206.85,1471.3) 7206.85,1417.38 7215.19,1409.04 ; v1@7210.64,1401.38 ccw(c7206.47,1409.04) 7215.19,1409.04 ; v1(7215.19,1393.04) 7215.19,1409.04 ; v1@7219.74,1401.38 cw(c7223.91,1409.04) 7215.19,1409.04
  Bottom Layer w4: NT6.1@7212.17,1377.33 ccw(c7204.88,1384.62) v1@7215.19,1384.62 ; NT6.1@7215,1370 7215,1377.04 7215.19,1377.23 v1(7215.19,1393.04) ; v1@7215.19,1383.7 ccw(c7224.2,1383.7) NT6.1@7217.83,1377.33
DB_PROGRAM.ID3: NT7.1 U30.R1 | length 258.8
  Top Layer w8: v2@6813.15,2249.7 cw(c6813.15,2227.97) 6828.51,2243.34 cw(c6843.88,2258.7) v2@6822.15,2258.7 ; v2(6813.15,2258.7) U30.R1@6832.83,2239.02 ; U30.R1@6826.99,2239.02 ccw(c6812.89,2239.02) 6822.86,2248.99 ccw(c6832.83,2258.96) U30.R1@6832.83,2244.86
  Bottom Layer w4: NT7.1@6800,2326.5 cw(c6800,2305.98) 6814.51,2320.49 ; NT7.1@6800,2330.5 cw(c6800,2319.64) 6807.68,2327.32 ; NT7.1@6800,2335 6813.15,2321.85 v2(6813.15,2258.7) ; v2@6805.37,2266.48 ccw(c6786.59,2285.26) 6813.15,2285.26 ccw(c6839.7,2285.26) v2@6820.93,2266.48 ; v2@6808.2,2263.65 ccw(c6796.25,2275.6) 6813.15,2275.6 ; 6813.15,2275.6 ccw(c6830.05,2275.6) v2@6818.1,2263.65
DB_PROGRAM.INIT: R76.1 U8.AA15 U30.U3 | length 10757.2
  Top Layer w4: U8.AA15@5449.06,3887.22 cw(c5449.06,3869.12) 5461.86,3881.92 cw(c5474.66,3894.72) U8.AA15@5456.56,3894.72 ; U8.AA15@5449.06,3887.38 cw(c5449.06,3869.66) 5461.59,3882.19 cw(c5474.12,3894.72) U8.AA15@5456.4,3894.72 ; U8.AA15@5449.06,3894.72 v3(5468.74,3875.04) ; 5455.94,3887.84 cw(c5443.13,3875.04) 5461.24,3875.04 ccw(c5443.13,3875.04) 5455.94,3887.84 ; 5455.94,3887.84 ccw(c5468.74,3900.65) 5468.74,3882.54 cw(c5468.74,3900.65) 5455.94,3887.84
  Top Layer w8: v2@6734.41,2170.96 cw(c6734.41,2149.23) 6749.77,2164.6 cw(c6765.14,2179.96) v2@6743.41,2179.96 ; v2(6734.41,2179.96) U30.U3@6754.09,2160.28 ; U30.U3@6748.25,2160.28 ccw(c6734.15,2160.28) 6744.12,2170.25 ccw(c6754.09,2180.22) U30.U3@6754.09,2166.12
  MidLayer1 w4: v3@5468.09,3867.57 cw(c5466.51,3849.53) 5480.38,3861.17 ; v3@5476.21,3874.39 ccw(c5494.25,3872.81) 5480.38,3861.17 ; 5492.6,3798.23 5492.6,3812.16 ; v1(5498.52,3008.37) 5498.52,3136.36 5506.86,3144.69 5506.86,3211.35 5481.86,3236.35 5481.86,3360.69 5523.52,3402.36 5523.52,3501.29 5497.31,3527.5 5492.75,3527.5 5482.5,3537.75 5482.5,3595.12 5481.5,3596.12 5481.5,3624.98 5492.6,3636.08 5492.6,3660 5492.6,3670 5492.6,3718.62 5492.6,3738.04 5492.6,3812.16 ; v1@5525.14,5119.09 ccw(c5508.92,5135.31) 5531.86,5135.31 ccw(c5554.79,5135.31) v1@5538.57,5119.09 ; v1@5527.97,5116.26 ccw(c5518.58,5125.65) 5531.86,5125.65 ccw(c5545.14,5125.65) v1@5535.75,5116.26 ; v1(5531.86,5112.37) 5531.86,5285.75 5690.19,5444.08 5690.19,5530.19 5810.04,5650.04 6442.56,5650.04 6818.6,5274 7324.56,5274 v1(7555.52,5043.04) ; v2@6723.41,2179.96 ccw(c6696.85,2179.96) 6715.63,2198.74 ccw(c6734.41,2217.51) v2@6734.41,2190.96 ; v2@6727.41,2179.96 ccw(c6710.51,2179.96) 6722.46,2191.91 ccw(c6734.41,2203.86) v2@6734.41,2186.96 ; v2(6734.41,2179.96) 6715.19,2199.18 6715.19,2308.37 6781.86,2375.04 6781.86,2516.71 6798.94,2533.79 6890,2533.79 6956.86,2600.65 6956.86,2765.71 v1(7016.19,2825.04) ; v1@7006.69,2825.04 cw(c6983.76,2825.04) 6999.97,2808.82 cw(c7016.19,2792.61) v1@7016.19,2815.54 ; v1@7010.69,2825.04 cw(c6997.41,2825.04) 7006.8,2815.65 cw(c7016.19,2806.26) v1@7016.19,2819.54 ; v1(7073.52,2791.71) 7159.23,2791.71 7265.19,2897.67 7265.19,3058.37 7298.52,3091.71 7298.52,4146.71 7336.78,4184.97 7348.86,4197.04 7348.86,4330.17 7399.86,4381.17 7399.86,4465.14 7372.52,4492.48 7372.52,4524.04 7373.52,4525.04 7373.52,4633.37 7372.52,4634.37 7372.52,4717.52 7463.21,4808.21 7489.83,4808.21 7515,4833.37 v1(7549.52,4833.37) ; v1@7077.41,2787.82 cw(c7086.8,2778.43) 7086.8,2791.71 cw(c7086.8,2804.99) v1@7077.41,2795.6 ; v1@7080.24,2784.99 cw(c7096.46,2768.77) 7096.46,2791.71 cw(c7096.46,2814.64) v1@7080.24,2798.43 ; v1@7542.81,4826.66 ccw(c7526.59,4810.44) 7526.59,4833.37 ccw(c7526.59,4856.31) v1@7542.81,4840.09 ; v1@7545.64,4829.49 ccw(c7536.25,4820.1) 7536.25,4833.37 ccw(c7536.25,4846.65) v1@7545.64,4837.26 ; v1@7546.02,5043.04 ccw(c7523.09,5043.04) 7539.31,5059.26 ccw(c7555.52,5075.48) v1@7555.52,5052.54 ; v1@7550.02,5043.04 ccw(c7536.75,5043.04) 7546.14,5052.43 ccw(c7555.52,5061.82) v1@7555.52,5048.54 ; 5480.38,3861.17 cw(c5450.87,3831.66) 5492.6,3831.66 5492.6,3812.16
  MidLayer2 w4: v1(5498.52,3008.37) 5571.67,3008.37 5580,3016.71 5630.86,3016.71 5639.19,3008.37 5639.19,2860.04 5641.86,2857.37 5731.86,2857.37 5748.52,2874.04 5748.52,2958.37 5765.19,2975.04 5790.19,2975.04 5806.86,2958.37 5806.86,2925.04 5798.52,2916.71 5798.52,2885.37 5850.52,2833.37 6313.19,2833.37 6338.19,2858.37 6573.52,2858.37 6631.86,2800.04 6631.86,2314.04 6583.52,2265.71 6515.19,2265.71 6506.86,2257.37 6506.86,2188.14 6534.29,2160.71 6715.16,2160.71 v2(6734.41,2179.96) ; v1@5502.41,3004.49 cw(c5511.8,2995.1) 5511.8,3008.37 cw(c5511.8,3021.65) v1@5502.41,3012.26 ; v1@5505.24,3001.66 cw(c5521.46,2985.44) 5521.46,3008.37 cw(c5521.46,3031.31) v1@5505.24,3015.09 ; v2@6723.41,2179.96 cw(c6696.85,2179.96) 6715.63,2161.18 cw(c6734.41,2142.41) v2@6734.41,2168.96 ; v2@6727.41,2179.96 cw(c6710.51,2179.96) 6722.46,2168.01 cw(c6734.41,2156.06) v2@6734.41,2172.96
  Bottom Layer w4: R76.1@5418.68,5085 5449.56,5085 5467.86,5066.71 5523.52,5066.71 5531.86,5075.04 v1(5531.86,5112.37) ; R76.1@5422.44,5081.24 cw(c5431.52,5072.16) 5431.52,5085 cw(c5431.52,5097.84) R76.1@5422.44,5088.76 ; R76.1@5425.27,5078.41 cw(c5441.18,5062.5) 5441.18,5085 cw(c5441.18,5107.5) R76.1@5425.27,5091.59 ; v1@5525.14,5105.66 cw(c5508.92,5089.44) 5531.86,5089.44 cw(c5554.79,5089.44) v1@5538.57,5105.66 ; v1@5527.97,5108.49 cw(c5518.58,5099.1) 5531.86,5099.1 cw(c5545.14,5099.1) v1@5535.75,5108.49 ; v1@7016.19,2815.54 cw(c7016.19,2792.61) 7032.41,2808.82 cw(c7048.63,2825.04) v1@7025.69,2825.04 ; v1@7016.19,2819.54 cw(c7016.19,2806.26) 7025.58,2815.65 cw(c7034.97,2825.04) v1@7021.69,2825.04 ; v1(7016.19,2825.04) 7049.52,2791.71 v1(7073.52,2791.71) ; v1@7066.81,2784.99 ccw(c7050.59,2768.77) 7050.59,2791.71 ccw(c7050.59,2814.64) v1@7066.81,2798.43 ; v1@7069.64,2787.82 ccw(c7060.25,2778.43) 7060.25,2791.71 ccw(c7060.25,2804.99) v1@7069.64,2795.6 ; v1@7542.81,4840.09 ccw(c7526.59,4856.31) 7549.52,4856.31 ccw(c7572.46,4856.31) v1@7556.24,4840.09 ; v1@7545.64,4837.26 ccw(c7536.25,4846.65) 7549.52,4846.65 ccw(c7562.8,4846.65) v1@7553.41,4837.26 ; v1@7548.81,5036.32 cw(c7532.59,5020.11) 7555.52,5020.11 cw(c7578.46,5020.11) v1@7562.24,5036.32 ; v1(7549.52,4833.37) 7549.52,4999 7555.52,5005 v1(7555.52,5043.04) ; v1@7551.64,5039.15 cw(c7542.25,5029.76) 7555.52,5029.76 cw(c7568.8,5029.76) v1@7559.41,5039.15
DB_PROGRAM.M0: R81.1 U30.R5 | length 2535.3
  Top Layer w8: v2@6813.15,2092.22 cw(c6813.15,2070.49) 6828.51,2085.86 cw(c6843.88,2101.22) v2@6822.15,2101.22 ; v2(6813.15,2101.22) U30.R5@6832.83,2081.54 ; U30.R5@6826.99,2081.54 ccw(c6812.89,2081.54) 6822.86,2091.51 ccw(c6832.83,2101.48) U30.R5@6832.83,2087.38
  MidLayer1 w4: v1@5933.47,2868.32 cw(c5917.26,2852.11) 5940.19,2852.11 cw(c5963.13,2852.11) v1@5946.91,2868.32 ; v1@5936.3,2871.15 cw(c5926.91,2861.76) 5940.19,2861.76 cw(c5953.47,2861.76) v1@5944.08,2871.15 ; v1(5940.19,2875.04) 5940.19,2848.06 5915.19,2823.06 5915.19,2807.06 5921.69,2800.56 5921.69,2766.18 5915.19,2759.68 5915.19,2648.28 5989.52,2573.94 5989.52,2498.34 6062.82,2425.04 v1(6091.86,2425.04) ; v1@6085.14,2418.32 ccw(c6068.92,2402.11) 6068.92,2425.04 ccw(c6068.92,2447.98) v1@6085.14,2431.76 ; v1@6087.97,2421.15 ccw(c6078.58,2411.76) 6078.58,2425.04 ccw(c6078.58,2438.32) v1@6087.97,2428.93 ; v1(6245.19,2441.71) 6256.86,2430.04 6256.86,2175.31 6298.52,2133.65 6298.52,2017.37 6407.52,1908.37 6556.86,1908.37 v1(6573.52,1891.71) ; v1@6564.02,1891.71 ccw(c6541.09,1891.71) 6557.31,1907.93 ccw(c6573.52,1924.14) v1@6573.52,1901.21 ; v1@6568.02,1891.71 ccw(c6554.75,1891.71) 6564.14,1901.1 ccw(c6573.52,1910.49) v1@6573.52,1897.21
  MidLayer2 w4: v1(6091.86,2425.04) 6108.52,2441.71 v1(6245.19,2441.71) ; v1@6091.86,2430.54 ccw(c6091.86,2443.82) 6101.25,2434.43 ccw(c6110.64,2425.04) v1@6097.36,2425.04 ; v1@6091.86,2434.54 ccw(c6091.86,2457.48) 6108.07,2441.26 ccw(c6124.29,2425.04) v1@6101.36,2425.04 ; v1@6238.47,2434.99 ccw(c6222.26,2418.77) 6222.26,2441.71 ccw(c6222.26,2464.64) v1@6238.47,2448.43 ; v1@6241.3,2437.82 ccw(c6231.91,2428.43) 6231.91,2441.71 ccw(c6231.91,2454.99) v1@6241.3,2445.6
  Bottom Layer w4: R81.1@5921.59,2842.08 ccw(c5905.68,2857.99) 5928.18,2857.99 ccw(c5950.68,2857.99) R81.1@5934.77,2842.08 ; R81.1@5924.42,2839.25 ccw(c5915.34,2848.33) 5928.18,2848.33 ccw(c5941.02,2848.33) R81.1@5931.94,2839.25 ; R81.1@5928.18,2835 5928.18,2863.03 v1(5940.19,2875.04) ; v1@6573.52,1882.21 cw(c6573.52,1859.27) 6589.74,1875.49 cw(c6605.96,1891.71) v1@6583.02,1891.71 ; v1@6573.52,1886.21 cw(c6573.52,1872.93) 6582.91,1882.32 cw(c6592.3,1891.71) v1@6579.02,1891.71 ; v1(6573.52,1891.71) 6590.19,1875.04 6776.86,1875.04 6793.52,1891.71 6793.52,2081.59 v2(6813.15,2101.22) ; v2@6802.15,2101.22 cw(c6775.59,2101.22) 6794.37,2082.44 cw(c6813.15,2063.67) v2@6813.15,2090.22 ; v2@6806.15,2101.22 cw(c6789.25,2101.22) 6801.2,2089.27 cw(c6813.15,2077.32) v2@6813.15,2094.22
DB_PROGRAM.M1: R80.1 U30.V2 | length 1904.8
  Top Layer w8: v2@6695.04,2210.33 cw(c6695.04,2188.6) 6710.4,2203.97 cw(c6725.77,2219.33) v2@6704.04,2219.33 ; v2(6695.04,2219.33) U30.V2@6714.72,2199.65 ; U30.V2@6708.88,2199.65 ccw(c6694.78,2199.65) 6704.75,2209.62 ccw(c6714.72,2219.59) U30.V2@6714.72,2205.49
  MidLayer2 w4: v1@5990.19,2944.21 cw(c5990.19,2921.27) 6006.41,2937.49 cw(c6022.63,2953.71) v1@5999.69,2953.71 ; v1@5990.19,2948.21 cw(c5990.19,2934.93) 5999.58,2944.32 cw(c6008.97,2953.71) v1@5995.69,2953.71 ; v1(5990.19,2953.71) 6014.86,2929.04 6122.33,2929.04 6160,2966.71 6432.31,2966.71 6490.65,2908.37 6540.19,2908.37 6640.19,2808.37 6640.19,2311.04 6586.86,2257.71 6563.19,2257.71 6556.86,2251.37 6556.86,2227.04 6583.86,2200.04 6675.86,2200.04 6685.19,2209.37 6685.19,2209.48 v2(6695.04,2219.33) ; 6676.19,2200.37 ccw(c6657.23,2219.33) v2@6684.04,2219.33 ; 6676.44,2200.63 cw(c6695.04,2182.03) v2@6695.04,2208.33 ; 6683.02,2207.2 ccw(c6670.89,2219.33) v2@6688.04,2219.33 ; 6683.27,2207.45 cw(c6695.04,2195.69) v2@6695.04,2212.33
  Bottom Layer w4: R80.1@5928.18,2955 5929.47,2953.71 v1(5990.19,2953.71) ; R80.1@5931.94,2958.27 ccw(c5942.95,2969.28) 5942.95,2953.71 ; R80.1@5934.77,2947.92 cw(c5948.75,2933.94) 5948.75,2953.71 ; R80.1@5934.77,2961.1 ccw(c5952.61,2978.94) 5952.61,2953.71 ; v1@5983.47,2946.99 ccw(c5967.26,2930.77) 5967.26,2953.71 ccw(c5967.26,2976.64) v1@5983.47,2960.43 ; v1@5986.3,2949.82 ccw(c5976.91,2940.43) 5976.91,2953.71 ccw(c5976.91,2966.99) v1@5986.3,2957.6
DB_PROGRAM.M2: R79.1 U30.U5 | length 2582.6
  Top Layer w8: v2@6734.41,2092.22 cw(c6734.41,2070.49) 6749.77,2085.86 cw(c6765.14,2101.22) v2@6743.41,2101.22 ; v2(6734.41,2101.22) U30.U5@6754.09,2081.54 ; U30.U5@6748.25,2081.54 ccw(c6734.15,2081.54) 6744.12,2091.51 ccw(c6754.09,2101.48) U30.U5@6754.09,2087.38
  MidLayer1 w4: v1@5933.47,3159.99 cw(c5917.26,3143.77) 5940.19,3143.77 cw(c5963.13,3143.77) v1@5946.91,3159.99 ; v1@5936.3,3162.82 cw(c5926.91,3153.43) 5940.19,3153.43 cw(c5953.47,3153.43) v1@5944.08,3162.82 ; v1(5940.19,3166.71) 5940.19,3031 5950.19,3021 5950.19,2916.04 5957.86,2908.37 5957.86,2671.06 6065.19,2563.73 v1(6065.19,2483.37) ; v1@6058.47,2490.09 ccw(c6042.26,2506.31) 6065.19,2506.31 ccw(c6088.13,2506.31) v1@6071.91,2490.09 ; v1@6061.3,2487.26 ccw(c6051.91,2496.65) 6065.19,2496.65 ccw(c6078.47,2496.65) v1@6069.08,2487.26
  Bottom Layer w4: R79.1@5921.59,3082.08 ccw(c5916.93,3086.75) R79.1@5923.52,3086.75 ; 5923.52,3089.92 ccw(c5942.61,3089.92) R79.1@5929.11,3076.42 ; 5923.52,3099.58 ccw(c5952.26,3099.58) R79.1@5931.94,3079.25 ; 5923.52,3109.23 ccw(c5961.92,3109.23) R79.1@5934.77,3082.08 ; R79.1@5928.18,3075.04 5923.52,3075.04 5923.52,3150.04 v1(5940.19,3166.71) ; v1@5930.69,3166.71 cw(c5907.76,3166.71) 5923.97,3150.49 cw(c5940.19,3134.27) v1@5940.19,3157.21 ; v1@5934.69,3166.71 cw(c5921.41,3166.71) 5930.8,3157.32 cw(c5940.19,3147.93) v1@5940.19,3161.21 ; v1@6057.02,2478.53 ccw(c6048.52,2473.51) 6048.52,2483.37 ccw(c6048.52,2493.24) v1@6057.02,2488.21 ; v1(6065.19,2483.37) 5973.37,2483.37 5940.19,2450.19 5940.19,2133.69 6021.34,2052.54 6043.69,2030.19 6290,2030.19 6292.19,2032.37 6420.52,2160.71 6706.86,2160.71 6715.19,2152.37 6715.19,2125.04 6723.52,2116.71 6723.52,2101.21 v2(6734.41,2101.22)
